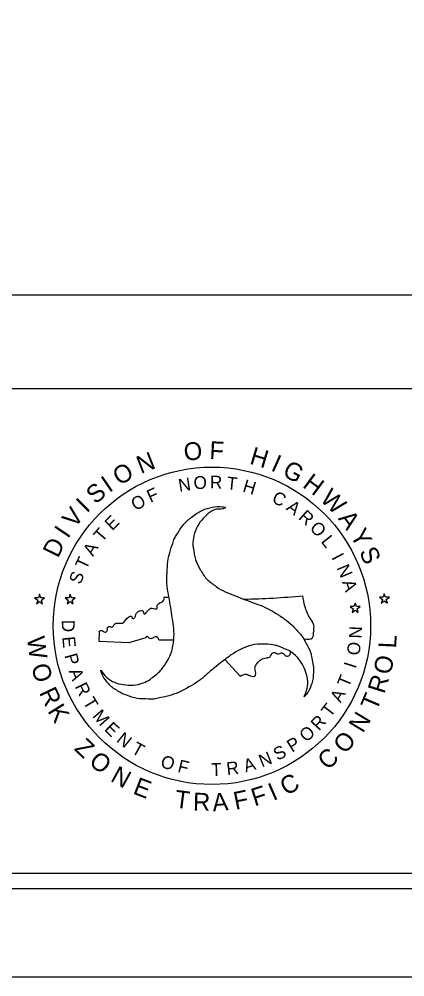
# Model space of a CAD drawing. Extents: x 768137 to 769825, y 651421 to 652521.
# Drawn here: x 769447.5 to 769556.9, y 651421.3 to 651692.7 of the extents above; entities that cross this region are included whole.
import ezdxf

# ---------------------------------------------------------------- set-up
doc = ezdxf.new("R2010")
doc.units = 0
for name, color, linetype in [('DEV BORDER CELL', 7, 'Continuous'), ('DEV DOT SWIRL SEAL CELL', 7, 'Continuous'), ('Scratch_Level_0', 7, 'Continuous'), ('Sheet Plot Border Outside CELL', 7, 'Continuous'), ('Text', 7, 'Continuous')]:
    doc.layers.add(name, color=color, linetype=linetype)

msp = doc.modelspace()

# ---------------------------------------------------------------- linework, layer by layer
at = {"layer": 'DEV BORDER CELL'}
for points in [[(769800.34, 652496.28), (768300.34, 652496.28), (768300.34, 651446.28), (769800.34, 651446.28)], [(769445.19, 651588.05), (769559.19, 651588.05), (769559.19, 651450.55), (769445.19, 651450.55)]]:
    msp.add_lwpolyline(points, close=True, dxfattribs=at)
at = {"layer": 'DEV DOT SWIRL SEAL CELL'}
for p, q in [((769551.05, 651529.86), (769550.73, 651528.85)), ((769551.41, 651528.85), (769551.05, 651529.86)), ((769451.92, 651528.71), (769452.8, 651528.07)), ((769453, 651528.71), (769451.92, 651528.71)), ((769452.8, 651528.07), (769452.48, 651527.03)), ((769452.48, 651527.03), (769453.32, 651527.67)), ((769453.32, 651529.72), (769453, 651528.71)), ((769453.68, 651528.71), (769453.32, 651529.72)), ((769453.32, 651527.67), (769454.21, 651527.03)), ((769453.32, 651527.67), (769454.21, 651527.03)), ((769454.77, 651528.71), (769453.68, 651528.71)), ((769453.89, 651528.07), (769454.77, 651528.71)), ((769453.89, 651528.07), (769454.77, 651528.71)), ((769454.21, 651527.03), (769453.89, 651528.07)), ((769454.21, 651527.03), (769453.89, 651528.07)), ((769461.68, 651528.7), (769460.6, 651528.7)), ((769460.6, 651528.7), (769461.48, 651528.06)), ((769461.48, 651528.06), (769461.16, 651527.01)), ((769461.16, 651527.01), (769462, 651527.66)), ((769462, 651529.7), (769461.68, 651528.7)), ((769462.36, 651528.7), (769462, 651529.7)), ((769462, 651527.66), (769462.89, 651527.01)), ((769463.45, 651528.7), (769462.36, 651528.7)), ((769462.56, 651528.06), (769463.45, 651528.7)), ((769462.89, 651527.01), (769462.56, 651528.06)), ((769542.77, 651527.21), (769542.45, 651526.21)), ((769543.13, 651526.21), (769542.77, 651527.21)), ((769550.73, 651528.85), (769549.64, 651528.85)), ((769549.64, 651528.85), (769550.53, 651528.21)), ((769550.53, 651528.21), (769550.2, 651527.17)), ((769550.2, 651527.17), (769551.05, 651527.81)), ((769551.05, 651527.81), (769551.93, 651527.17)), ((769552.49, 651528.85), (769551.41, 651528.85)), ((769551.61, 651528.21), (769552.49, 651528.85)), ((769551.93, 651527.17), (769551.61, 651528.21)), ((769542.45, 651526.21), (769541.37, 651526.21)), ((769541.37, 651526.21), (769542.25, 651525.57)), ((769542.25, 651525.57), (769541.93, 651524.53)), ((769541.93, 651524.53), (769542.77, 651525.17)), ((769542.77, 651525.17), (769543.65, 651524.53)), ((769544.22, 651526.21), (769543.13, 651526.21)), ((769543.33, 651525.57), (769544.22, 651526.21)), ((769543.65, 651524.53), (769543.33, 651525.57)), ((769470.25, 651516.27), (769470.33, 651518.92)), ((769478.64, 651515.96), (769470.25, 651516.27)), ((769483.44, 651517.37), (769478.64, 651515.96)), ((769487.14, 651516.81), (769491.36, 651516.77)), ((769505.89, 651511.19), (769510.2, 651506.52))]:
    msp.add_line(p, q, dxfattribs=at)
for start, end in [(265.6785, 265.9762), (271.2035, 275.3236)]:
    msp.add_arc((769506.28, 651761.45), 233.19, start, end, dxfattribs=at)
for points in [[(769470.66, 651508.16), (769472.4, 651506.14), (769474.58, 651504.75), (769477.07, 651504.1), (769479.89, 651503.94), (769482.76, 651504.61), (769484.67, 651505.58), (769485.47, 651506.22), (769486.87, 651507.33), (769487.86, 651508.4), (769489.53, 651510.76), (769490.82, 651513.55), (769491.35, 651516.75), (769491.38, 651517.02), (769491.35, 651520.02), (769490.95, 651523.06), (769490.52, 651525.98), (769489.98, 651529.01), (769489.5, 651532.02), (769489.45, 651534.95), (769489.64, 651538.3), (769490.12, 651541.18), (769491.06, 651544.13), (769491.57, 651545.53), (769492.27, 651546.65), (769494.01, 651549.31), (769496.29, 651551.45), (769497.8, 651552.59), (769499.22, 651553.34), (769499.46, 651553.47), (769502.31, 651554.38), (769505.1, 651554.49), (769506.04, 651554.25)], [(769506.12, 651554.33), (769506.04, 651554.25), (769503.46, 651553.77), (769501.13, 651552.56), (769499.33, 651550.73), (769497.8, 651548.4), (769496.94, 651545.55), (769496.8, 651543.43), (769496.99, 651542.41), (769497.23, 651540.64), (769497.64, 651539.24), (769498.9, 651536.64), (769500.64, 651534.12), (769503.17, 651532.05), (769503.38, 651531.89), (769505.96, 651530.41), (769508.83, 651529.23), (769511.57, 651528.16), (769514.44, 651527.11), (769517.28, 651525.98), (769519.86, 651524.59), (769522.68, 651522.76), (769524.91, 651520.91), (769527, 651518.63), (769527.97, 651517.47), (769528.59, 651516.29), (769530.04, 651513.47), (769530.73, 651510.41), (769530.98, 651508.53), (769530.92, 651506.92), (769530.92, 651506.65), (769530.25, 651503.73), (769528.94, 651501.26), (769528.29, 651500.59)], [(769470.33, 651518.92), (769470.25, 651519.18), (769470.7, 651519.46), (769471.94, 651518.95), (769472.56, 651519.49), (769472.53, 651520.03), (769473.04, 651520.56), (769473.89, 651520.39), (769474.65, 651521.36), (769475.36, 651521.55), (769476.86, 651521.55), (769478.64, 651523.33), (769479.37, 651523.45), (769479.57, 651522.96), (769480.02, 651522.88), (769480.81, 651524.35), (769481.01, 651524.55), (769482.37, 651525.11), (769482.73, 651524.83), (769482.85, 651524.18), (769483.04, 651524.07), (769483.5, 651524.38), (769484.12, 651525.17), (769485.25, 651525.76), (769486.55, 651525.59), (769486.77, 651526.67), (769488.3, 651527.68), (769488.61, 651528.31), (769488.7, 651528.93)], [(769528.22, 651517.04), (769530.69, 651517.34), (769531.05, 651519.29), (769531.08, 651520.93), (769530.06, 651522.83), (769528.54, 651526.3), (769527.92, 651529.27)], [(769487.14, 651516.81), (769486.8, 651517.46), (769486.13, 651517.65), (769485.19, 651517.17), (769484.51, 651517.2), (769483.75, 651517.77), (769483.44, 651517.37)], [(769528.29, 651500.59), (769529.15, 651503.06), (769529.29, 651505.66), (769528.59, 651508.16), (769527.33, 651510.65), (769525.31, 651512.8), (769523.54, 651513.98), (769522.55, 651514.33), (769520.94, 651515.03), (769519.46, 651515.35), (769516.61, 651515.59), (769513.53, 651515.32), (769510.49, 651514.17), (769510.25, 651514.06), (769507.68, 651512.53), (769505.23, 651510.68), (769502.9, 651508.86), (769500.56, 651506.87), (769498.17, 651504.94), (769495.68, 651503.43), (769492.67, 651501.9), (769489.96, 651500.91), (769486.95, 651500.24), (769485.45, 651499.97), (769484.13, 651500.02), (769480.99, 651500.19), (769477.96, 651501.1), (769476.24, 651501.82), (769474.87, 651502.71), (769474.63, 651502.84), (769472.43, 651504.86), (769470.95, 651507.22), (769470.66, 651508.16)], [(769510.2, 651506.52), (769511.9, 651507.03), (769513.31, 651506.49), (769513.99, 651506.38), (769514.55, 651506.8), (769514.38, 651508.92), (769514.86, 651509.91), (769517.15, 651511.61), (769518.57, 651511.92), (769519.61, 651513.22), (769520.03, 651513.19), (769520.68, 651512.82), (769522.13, 651513.11), (769523.28, 651512.17), (769523.96, 651512.23), (769524.5, 651513.29)]]:
    msp.add_spline(points, degree=3, dxfattribs=at)
at = {"layer": 'Scratch_Level_0'}
msp.add_lwpolyline([(769750.34, 652446.28), (768350.34, 652446.28), (768350.34, 651496.28), (769229.19, 651496.28), (769229.19, 651614.55), (769750.34, 651614.55)], close=True, dxfattribs=at)
at = {"layer": 'Sheet Plot Border Outside CELL'}
msp.add_lwpolyline([(768137.34, 651421.28), (769825.34, 651421.28), (769825.34, 652521.28), (768137.34, 652521.28)], close=True, dxfattribs=at)
at = {"layer": 'Text'}
msp.add_circle((769502.19, 651520.76), 44.97, dxfattribs=at)

# ---------------------------------------------------------------- texts
at = {"layer": 'DEV DOT SWIRL SEAL CELL'}
for s, height, rotation, p in [('O', 5.04, 5.7649, (769494.45, 651567.49)), ('F', 5.04, 357.2575, (769501.4, 651568.04)), ('H', 5.04, 343.454, (769512.63, 651566.75)), ('N', 5.04, 21.5861, (769482.05, 651563.75)), ('I', 5.04, 335.804, (769518.63, 651564.88)), ('O', 5.04, 30.0935, (769475.94, 651560.38)), ('G', 5.04, 331.5167, (769521.86, 651563.49)), ('I', 5.04, 34.3808, (769473.06, 651558.35)), ('N', 3.63, 9.0227, (769492.97, 651558.7)), ('O', 3.63, 3.9446, (769497.11, 651559.42)), ('R', 3.63, 358.8665, (769501.59, 651559.69)), ('H', 5.04, 323.4632, (769527.61, 651560.24)), ('S', 5.04, 40.5848, (769469.2, 651555.04)), ('F', 3.63, 24.2569, (769484.75, 651555.58)), ('H', 3.63, 343.6322, (769510.67, 651558.83)), ('W', 5.04, 315.8133, (769532.61, 651556.44)), ('I', 5.04, 44.8722, (769466.74, 651552.51)), ('O', 3.63, 29.335, (769480.54, 651553.23)), ('C', 3.63, 333.4761, (769518.9, 651555.91)), ('V', 5.04, 51.5806, (769463.3, 651548.22)), ('A', 3.63, 323.3199, (769523, 651553.79)), ('E', 3.63, 44.5692, (769473.93, 651547.55)), ('R', 3.63, 318.2418, (769526.49, 651551.23)), ('A', 5.04, 306.7762, (769537.79, 651551.14)), ('I', 5.04, 55.8679, (769461.37, 651545.27)), ('T', 3.63, 49.6473, (769471.07, 651544.24)), ('O', 3.63, 313.1637, (769529.7, 651548.32)), ('Y', 5.04, 299.7484, (769541.21, 651546.49)), ('L', 3.63, 308.0856, (769532.92, 651544.64)), ('D', 5.04, 63.459, (769458.52, 651539.74)), ('A', 3.63, 59.8035, (769468.51, 651540.25)), ('T', 3.63, 64.8816, (769466.57, 651536.46)), ('I', 3.63, 297.9295, (769535.96, 651540.14)), ('S', 5.04, 293.2249, (769543.85, 651541.84)), ('N', 3.63, 292.8514, (769537.48, 651537.23)), ('S', 3.63, 69.9597, (769464.98, 651532.32)), ('A', 3.63, 287.7733, (769539.08, 651533.18)), ('D', 3.63, 270.272, (769459.64, 651522.46)), ('N', 3.63, 87.733, (769544.63, 651517.1)), ('E', 3.63, 275.3501, (769459.75, 651517.6)), ('O', 3.63, 82.9269, (769544, 651512.23)), ('P', 3.63, 285.5063, (769460.36, 651512.39)), ('I', 3.63, 72.7707, (769542.92, 651508.47)), ('A', 3.63, 290.5843, (769461.56, 651507.93)), ('T', 3.63, 67.6926, (769540.93, 651503.08)), ('R', 3.63, 295.6624, (769463.23, 651503.6)), ('T', 3.63, 300.7405, (769465.51, 651499.19)), ('A', 3.63, 62.6145, (769538.7, 651498.74)), ('M', 3.63, 310.8967, (769468.13, 651495.1)), ('T', 3.63, 52.4584, (769535.75, 651494.6)), ('R', 3.63, 47.3803, (769532.49, 651490.85)), ('E', 3.63, 315.9748, (769471.47, 651491.28)), ('O', 3.63, 42.3022, (769528.96, 651487.59)), ('N', 3.63, 321.0529, (769474.89, 651488.12)), ('P', 3.63, 32.146, (769524.89, 651484.77)), ('T', 3.63, 331.209, (769479.13, 651484.88)), ('S', 3.63, 27.068, (769520.76, 651482.46)), ('O', 3.63, 341.3652, (769487.34, 651480.86)), ('N', 3.63, 21.9899, (769516.35, 651480.59)), ('F', 3.63, 346.4433, (769492.26, 651479.38)), ('T', 3.63, 1.6775, (769502.02, 651478.19)), ('R', 3.63, 6.7556, (769506.51, 651478.43)), ('A', 3.63, 16.9118, (769511.77, 651479.2))]:
    msp.add_text(s, height=height, rotation=rotation, dxfattribs=at).set_placement(p)
at = {"layer": 'Text'}
for s, height, rotation, p in [('T', 3.63, 353.7884, (769506.22, 651559.47)), ('W', 5.04, 278.15, (769449.71, 651517.38)), ('L', 5.04, 87.429, (769554.39, 651514.31)), ('O', 5.04, 78.9896, (769552.88, 651506.72)), ('O', 5.04, 287.1147, (769450.87, 651509.25)), ('R', 5.04, 72.7519, (769551.05, 651501.29)), ('R', 5.04, 295.5541, (769453.12, 651501.84)), ('T', 5.04, 66.881, (769548.8, 651496.4)), ('K', 5.04, 301.7918, (769455.46, 651496.62)), ('N', 5.04, 58.892, (769544.97, 651490.15)), ('Z', 5.04, 316.1688, (769462.92, 651485.77)), ('O', 5.04, 50.4526, (769540.01, 651484.21)), ('O', 5.04, 322.5233, (769467.03, 651481.64)), ('C', 5.04, 43.0807, (769535.01, 651479.66)), ('N', 5.04, 330.9626, (769473.15, 651476.9)), ('C', 5.04, 28.0033, (769523.19, 651472.53)), ('E', 5.04, 338.9517, (769479.53, 651473.29)), ('F', 5.04, 17.7627, (769514.28, 651469.57)), ('I', 5.04, 23.7503, (769519.55, 651471.11)), ('T', 5.04, 352.6948, (769491.46, 651469.27)), ('R', 5.04, 358.5656, (769496.78, 651468.44)), ('A', 5.04, 4.8034, (769502.49, 651468.16)), ('F', 5.04, 11.7751, (769508.88, 651468.59))]:
    msp.add_text(s, height=height, rotation=rotation, dxfattribs=at).set_placement(p)

doc.saveas('drawing.dxf')
